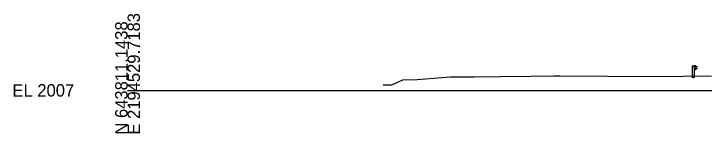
# Model space of a CAD drawing. Extents: x -26 to 303, y -10 to 11030.
# Drawn here: x -25.7 to 130.2, y 7490.3 to 7517.3 of the extents above; entities that cross this region are included whole.
import ezdxf

# ---------------------------------------------------------------- set-up
doc = ezdxf.new("R2010")
doc.units = 0
for name, color, linetype in [('DESIGN - SHEET - Light Grid', 7, 'Continuous'), ('DESIGN - TYPICAL - Guardrail', 7, 'Continuous'), ('SURVEY - GROUND - Top of Ground', 7, 'Continuous')]:
    doc.layers.add(name, color=color, linetype=linetype)

msp = doc.modelspace()

# ---------------------------------------------------------------- linework, layer by layer
at = {"layer": 'DESIGN - SHEET - Light Grid'}
msp.add_line((0, 7500), (150, 7500), dxfattribs=at)
at = {"layer": 'DESIGN - TYPICAL - Guardrail'}
for p, q in [((127.57, 7504.73), (127.57, 7504.73)), ((127.57, 7504.73), (127.57, 7504.73)), ((127.97, 7504.73), (127.97, 7504.73)), ((127.97, 7504.73), (127.97, 7504.73)), ((127.67, 7502.91), (127.57, 7502.84)), ((127.85, 7502.9), (127.76, 7502.93)), ((127.97, 7502.94), (127.92, 7502.91))]:
    msp.add_line(p, q, dxfattribs=at)
for points in [[(127.57, 7502.84), (127.57, 7505.53), (127.97, 7505.53), (127.97, 7502.94)], [(127.97, 7504.75), (128.37, 7504.75), (128.37, 7505.53), (127.97, 7505.53)], [(128.37, 7505.5), (128.44, 7505.49), (128.58, 7505.39), (128.6, 7505.36), (128.58, 7505.33), (128.39, 7505.21), (128.37, 7505.18), (128.37, 7505.1), (128.39, 7505.07), (128.58, 7504.95), (128.6, 7504.92), (128.58, 7504.88), (128.44, 7504.79), (128.37, 7504.78)]]:
    msp.add_lwpolyline(points, dxfattribs=at)
for centre, start, end in [((127.73, 7502.83), 74.0986, 124.6952), ((127.87, 7503), 254.0986, 298.996)]:
    msp.add_arc(centre, 0.1, start, end, dxfattribs=at)
at = {"layer": 'SURVEY - GROUND - Top of Ground'}
msp.add_lwpolyline([(57.76, 7501.28), (59.68, 7501.26), (62.2, 7502.35), (65.43, 7502.49), (72.93, 7503.03), (78.3, 7503.08), (84.33, 7503.14), (91.06, 7503.23), (96.24, 7503.27), (97.72, 7503.25), (119.06, 7503.16), (131.86, 7503.32)], dxfattribs=at)

# ---------------------------------------------------------------- texts
at = {"layer": 'DESIGN - SHEET - Light Grid'}
for s, p in [('E 2194529.7183', (2.8, 7490)), ('N 643811.1438', (0, 7490))]:
    msp.add_text(s, height=2.8, rotation=90, dxfattribs=at).set_placement(p)
msp.add_text('EL 2007', height=2.8, dxfattribs=at).set_placement((-26, 7498.6))

doc.saveas('drawing.dxf')
